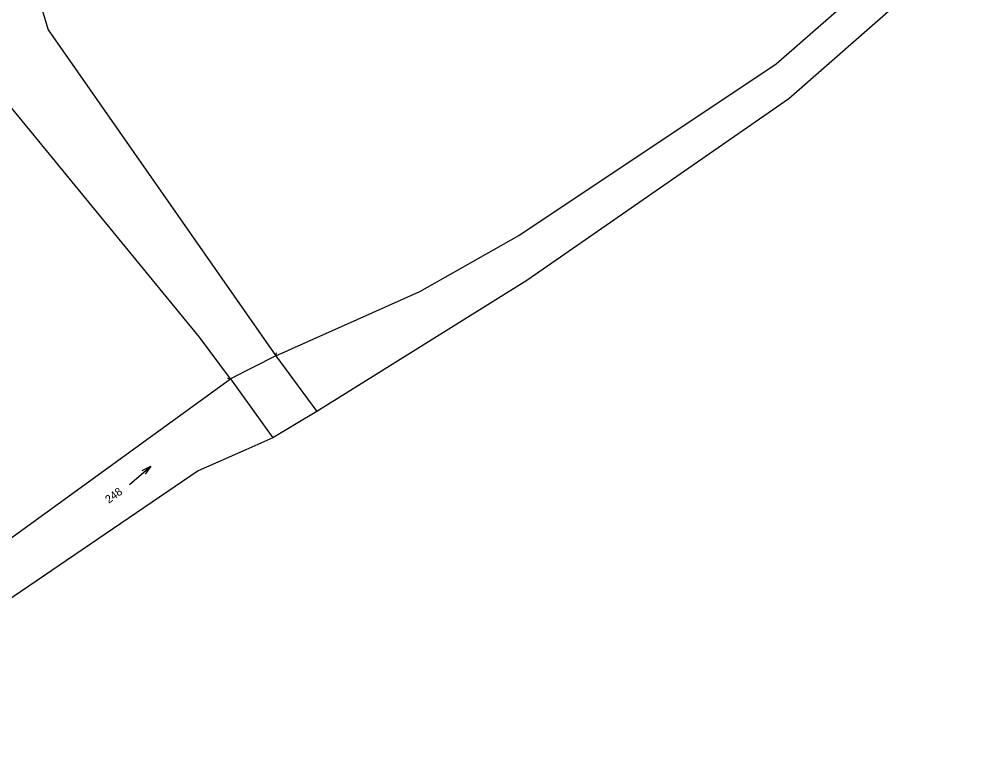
# Model space of a CAD drawing. Extents: x -811039 to -805820, y -1161436 to -1155864.
# Drawn here: x -810537.2 to -810331.8, y -1161202.3 to -1161047.6 of the extents above; entities that cross this region are included whole.
import ezdxf

# ---------------------------------------------------------------- set-up
doc = ezdxf.new("R2010")
doc.units = 0
for name, color, linetype in [('Default', 7, 'Continuous'), ('Hranice kat_území', 7, 'Continuous'), ('Hranice parcel', 7, 'Continuous'), ('Parcelní čísla', 7, 'Continuous'), ('Vnitřní kresba', 7, 'Continuous'), ('Značky kultur', 7, 'Continuous')]:
    doc.layers.add(name, color=color, linetype=linetype)

# ---------------------------------------------------------------- blocks, each defined once
blk = doc.blocks.new('802')
at = {"layer": 'Default'}
blk.add_line((-3, 0), (3, 0), dxfattribs=at)
blk.add_lwpolyline([(1, 0.5), (3, 0), (1, -0.5)], dxfattribs=at)
blk = doc.blocks.new('4201')
at = {"layer": 'Default'}
blk.add_line((0, 0), (-0.5, -0.5), dxfattribs=at)

msp = doc.modelspace()

# ---------------------------------------------------------------- linework, layer by layer
at = {"layer": 'Hranice kat_území'}
for p, q in [((-810331.78, -1161027.66), (-810373.79, -1161064.42)), ((-810373.79, -1161064.42), (-810429.4, -1161103.02)), ((-810429.4, -1161103.02), (-810474.03, -1161130.86)), ((-810474.03, -1161130.86), (-810478.44, -1161133.5)), ((-810478.44, -1161133.5), (-810483.33, -1161136.43)), ((-810483.33, -1161136.43), (-810489.09, -1161138.98)), ((-810489.09, -1161138.98), (-810499.25, -1161143.49)), ((-810499.25, -1161143.49), (-810585.62, -1161202.26))]:
    msp.add_line(p, q, dxfattribs=at)
at = {"layer": 'Hranice parcel'}
for p, q in [((-810376.47, -1161057.05), (-810353.34, -1161036.78)), ((-810532.44, -1161045.37), (-810531.08, -1161049.77)), ((-810531.08, -1161049.77), (-810482.7, -1161119.07)), ((-810431.16, -1161093.49), (-810376.47, -1161057.05)), ((-810498.94, -1161115.1), (-810540.78, -1161064.04)), ((-810452.13, -1161105.39), (-810431.16, -1161093.49)), ((-810482.7, -1161119.07), (-810452.13, -1161105.39)), ((-810492.32, -1161123.89), (-810498.94, -1161115.1)), ((-810482.7, -1161119.07), (-810492.32, -1161123.89)), ((-810562.67, -1161174.91), (-810492.32, -1161123.89))]:
    msp.add_line(p, q, dxfattribs=at)
at = {"layer": 'Vnitřní kresba'}
for p, q in [((-810482.7, -1161119.07), (-810474.03, -1161130.86)), ((-810492.32, -1161123.89), (-810483.33, -1161136.43))]:
    msp.add_line(p, q, dxfattribs=at)

# ---------------------------------------------------------------- block references
for p, rotation in [((-810482.7, -1161119.07), -146.8597), ((-810492.32, -1161123.89), -49.91524100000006)]:
    msp.add_blockref('4201', p, dxfattribs=dict(at, rotation=rotation))
at = {"layer": 'Značky kultur', "rotation": 40.45082}
msp.add_blockref('802', (-810511.54, -1161144.43), dxfattribs=at)

# ---------------------------------------------------------------- texts
at = {"layer": 'Parcelní čísla'}
msp.add_text('248', height=1.7, rotation=36.326, dxfattribs=at).set_placement((-810518.2, -1161150.48))

doc.saveas('drawing.dxf')
